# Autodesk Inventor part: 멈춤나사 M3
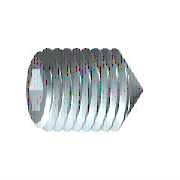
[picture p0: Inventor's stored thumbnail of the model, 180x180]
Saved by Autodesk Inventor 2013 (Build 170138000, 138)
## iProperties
Created: 2012-02
Part Number: 멈춤나사 M3
Material: 강철, 연강
Description: 6각 소켓 머리 없는 멈춤 나사
Document SubType Name: Modeling
Standard: KS B 1028
Designer: test
Standards Organization: KS
Language: ko-KR
Size Designation: 원추점 M3x8
Categories: <MemberInstance><Categories><Category DisplayName="조임쇠" InternalName="e4da775c-781d-43d5-af7c-5136215cf5a6" Mnemonic="FSTN"><Category DisplayName="볼트" InternalN
Density: 1 g/cm^3
IsCustomPart: 1
Author: test
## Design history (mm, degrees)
sketch "스케치1"
  geometry: L1 (0, 0)-(5.5, 0); L2 (8, 0.866)-(8, 1.5); L3 (8, 1.5)-(0, 1.5); L4 (8, 0.866)-(6, 0.866); L5 (6, 0.866)-(5.5, 0); L6 (0, -0.3)-(0, 1.8) reference; L7 (0, 1.5)-(0, 0)
  constraints: 13 end point, 3 parallel, 1 collinear, 1 perpendicular, 1 point on line
  dimensions: "d0" = 2 distance of L2.start L4.end (= INTI); "d1" = 60 deg angle of L5 L1; "d2" = 3 diameter of L3 L1 (= NND); "d3" = 1.73205 diameter of L4 L1 (= 1.1547 x SW); "d5" = 8 distance from line of L2 L3.end (= NLG)
revolve "본체" sketch "스케치1" stored, may be unused: angle "d6" = 90 deg
sketch "스케치2"
  geometry: L1 (-0.433, 0.75)-(0.433, 0.75); L2 (0.433, 0.75)-(0.866, 0); L3 (0.866, 0)-(0.433, -0.75); L4 (0.433, -0.75)-(-0.433, -0.75); L5 (-0.433, -0.75)-(-0.866, 0); L6 (-0.866, 0)-(-0.433, 0.75); 3 further points
  constraints: 12 end point, 1 coincident, 1 horizontal, 13 other
extrude "슬롯" join sketch "스케치2" taper "d7" = 0 deg; stored distance "d21" = 10
workaxis "Work Axis1"
workplane "Work Plane1"
sketch "스케치4"
  geometry: L1 (0, 0.15)-(-1.35, 1.5) reference; L2 (0, -0.15)-(-1.35, -1.5) reference; L3 (-1.35, -1.5)-(0.15, 0); L4 (-1.35, 1.5)-(0.15, 0); 2 further points
  constraints: 4 end point, 1 coincident, 1 collinear, 1 horizontal alignment
body "Solid1"
feature "스레드" dims "d12" = 8 (= NLG), "d13" = 0
chamfer "모따기1" distance "d8" = 1.35 (computed from NND, SPD, FAWI); stored, may be unused: angle "d9" = 45 deg (= FAWI), second distance "d34" = 1.35 (computed from NND, SPD, FAWI)
chamfer "모따기2" distance "d10" = 0.30673 (= -0.5 x GD1 + 0.5 x NND); stored, may be unused: angle "d11" = 45 deg (= FAWI), second distance "d35" = 0.30673 (= -0.5 x GD1 + 0.5 x NND)
other parameters: "NND" = 3 [user parameter; used in 5 equation terms], "NLG" = 8 [user parameter; used in 2 equation terms], "INTI" = 2 [user parameter; used in 1 equation term], "FAWI" = 45 deg [user parameter; used in 4 equation terms], "SW" = 1.5 [user parameter; used in 2 equation terms], "GD1" = 2.38655 (= THREADDIA - 1.2269 x PTC) [user parameter; used in 2 equation terms], "d4" = 0, "FAWI1" = 45 deg [user parameter], "SPD" = 0.3 [user parameter; used in 2 equation terms], "d36" = 0, "d37" = 0, "GUL" = 0.30673 (= 0.61345 x PTC) [user parameter], "TOA" = 30 deg [user parameter], "THREADDIA" = 3 [user parameter; used in 1 equation term], "PTC" = 0.5 [user parameter; used in 4 equation terms], "GAL" = 0.30673 (= 0.61345 x PTC) [user parameter], "E0" = 1.7325 (= 1.155 x SW) [user parameter]
